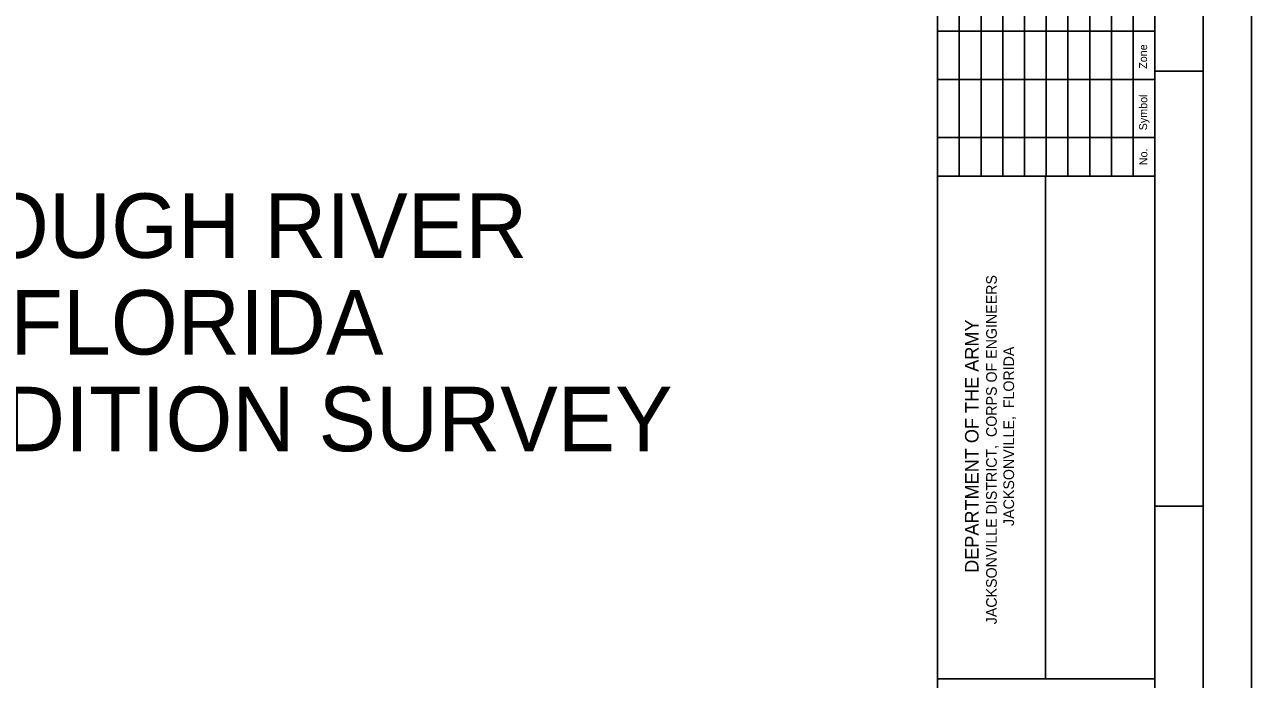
# Model space of a CAD drawing. Extents: x 492225 to 553725, y 1303773 to 1347273.
# Drawn here: x 534669 to 553725, y 1322833 to 1332996 of the extents above; entities that cross this region are included whole.
import ezdxf

# ---------------------------------------------------------------- set-up
doc = ezdxf.new("R2010")
doc.units = 0
for name, color, linetype in [('G-ANNO-TEXT', 7, 'Continuous'), ('G-ANNO-TTLB', 7, 'Continuous'), ('Level 1', 7, 'Continuous')]:
    doc.layers.add(name, color=color, linetype=linetype)

msp = doc.modelspace()

# ---------------------------------------------------------------- linework, layer by layer
at = {"layer": 'G-ANNO-TTLB'}
for p, q in [((552975.069, 1304522.564), (552975.069, 1346522.564)), ((548850.069, 1305272.564), (548850.069, 1345772.564)), ((552225.069, 1345772.564), (552225.069, 1305272.564)), ((549187.569, 1330642.064), (549187.569, 1342640.564)), ((549525.069, 1330642.064), (549525.069, 1342640.564)), ((549862.569, 1330642.064), (549862.569, 1342640.564)), ((550200.069, 1330642.064), (550200.069, 1342640.564)), ((550537.569, 1330642.064), (550537.569, 1342640.564)), ((550875.069, 1330642.064), (550875.069, 1342640.564)), ((551212.569, 1330642.064), (551212.569, 1342640.564)), ((551550.069, 1330642.064), (551550.069, 1342640.564)), ((551887.569, 1330642.064), (551887.569, 1342640.564)), ((548850.069, 1332892.064), (552225.069, 1332892.064)), ((552975.069, 1332272.564), (552225.069, 1332272.564)), ((548850.069, 1332142.064), (552225.069, 1332142.064)), ((548850.069, 1331242.064), (552225.069, 1331242.064)), ((550525.569, 1330642.064), (550525.569, 1322843.564)), ((552975.069, 1325522.564), (552225.069, 1325522.564)), ((552225.069, 1322843.564), (548850.069, 1322843.564))]:
    msp.add_line(p, q, dxfattribs=at)
for points in [[(492225.069, 1303772.564), (553725.069, 1303772.564), (553725.069, 1347272.564), (492225.069, 1347272.564)], [(492225.069, 1303772.564), (553725.069, 1303772.564), (553725.069, 1347272.564), (492225.069, 1347272.564)], [(492225.069, 1347272.564), (553725.069, 1347272.564), (553725.069, 1303772.564), (492225.069, 1303772.564)]]:
    msp.add_lwpolyline(points, close=True, dxfattribs=at)
msp.add_lwpolyline([(552225.069, 1330642.064), (548850.069, 1330642.064)], dxfattribs=at)

# ---------------------------------------------------------------- texts
at = {"layer": 'G-ANNO-TEXT'}
for s, height, rotation, p in [('Zone', 124.488, 89.66090001, (552102.069, 1332308.564)), ('Symbol', 124.488, 89.66090001, (552103.569, 1331354.564)), ('No.', 124.497, 89.66090001, (552108.069, 1330813.064)), ('JACKSONVILLE DISTRICT,  CORPS OF ENGINEERS', 164.988, 90, (549769.569, 1323689.564)), ('DEPARTMENT OF THE ARMY', 209.988, 90, (549486.069, 1324487.564)), ('JACKSONVILLE,  FLORIDA', 164.988, 90, (550038.069, 1325215.064))]:
    msp.add_text(s, height=height, rotation=rotation, dxfattribs=at).set_placement(p)
at = {"layer": 'Level 1'}
for s, p in [('HILLSBOROUGH RIVER', (527393.388, 1329374.983)), ('TAMPA, FLORIDA', (529098.112, 1327874.983)), ('PROJECT CONDITION SURVEY', (524747.719, 1326374.982))]:
    msp.add_text(s, height=1000.000002, dxfattribs=at).set_placement(p)

doc.saveas('drawing.dxf')
